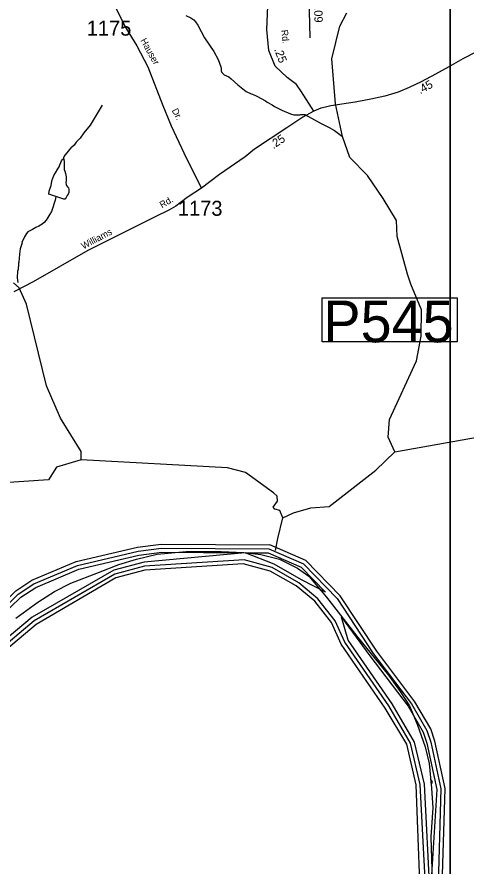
# Model space of a CAD drawing. Extents: x 1551653 to 1702041, y 811336 to 920032.
# Drawn here: x 1564838 to 1569264, y 841832 to 850193 of the extents above; entities that cross this region are included whole.
import ezdxf

# ---------------------------------------------------------------- set-up
doc = ezdxf.new("R2010")
doc.units = 0
for name, color, linetype in [('Old_Level_11', 7, 'Continuous'), ('Old_Level_17', 7, 'Continuous'), ('Old_Level_31', 7, 'Continuous'), ('Old_Level_32', 7, 'Continuous'), ('Old_Level_50', 7, 'Continuous'), ('Old_Level_52', 7, 'Continuous'), ('Old_Level_59', 7, 'Continuous'), ('Old_Level_60', 7, 'Continuous'), ('Old_Level_61', 7, 'Continuous'), ('Old_Level_62', 7, 'Continuous'), ('Old_Level_63', 7, 'Continuous'), ('Old_Level_8', 7, 'Continuous')]:
    doc.layers.add(name, color=color, linetype=linetype)

msp = doc.modelspace()

# ---------------------------------------------------------------- linework, layer by layer
at = {"layer": 'Old_Level_31'}
for p, q in [((1567981.814, 849323.404), (1567981.814, 849323.404)), ((1564859.91, 847517.633), (1564859.91, 847517.633))]:
    msp.add_line(p, q, dxfattribs=at)
msp.add_lwpolyline([(1567839.253, 847428.797), (1569167.183, 847428.797), (1569167.183, 846995.197), (1567839.253, 846995.197), (1567839.253, 847428.797)], dxfattribs=at)
at = {"layer": 'Old_Level_32'}
msp.add_line((1567706.962, 850436.136), (1567717.001, 849989.026), dxfattribs=at)
for points in [[(1565698.08, 850504.18), (1565911.883, 850079.073), (1566016.485, 849907.988), (1566123.637, 849701.155), (1566271.611, 849320.682), (1566353.167, 849120.476), (1566506.243, 848798.734), (1566651.484, 848508.82)], [(1567756.465, 849267.101), (1567636.692, 849456.514), (1567586.499, 849526.846), (1567496.151, 849597.178), (1567375.688, 849707.699), (1567315.457, 849863.434), (1567295.379, 850069.405), (1567310.437, 850456.231)], [(1569862.061, 850145.2), (1569803.462, 850098.002), (1569761.06, 850068.599), (1569700.362, 850027.401), (1569651.861, 850002.201), (1569569.263, 849957.202), (1569468.361, 849904.702), (1569355.563, 849850.302), (1569222.561, 849780.201), (1569085.261, 849702.1), (1568952.361, 849630.102), (1568813.064, 849554.102), (1568694.163, 849499.702), (1568585.462, 849451.3), (1568454.862, 849413.102), (1568316.365, 849385.103), (1568163.964, 849355.303), (1567923.164, 849316.803), (1567870.966, 849305.602), (1567826.963, 849296.1), (1567756.465, 849267.101)], [(1567756.465, 849267.101), (1567713.965, 849243.801), (1567649.464, 849206.701), (1567490.064, 849103.004), (1567172.765, 848891.502), (1567080.109, 848815.621), (1566828.63, 848641.12), (1566733.43, 848568.42), (1566651.484, 848508.82)], [(1566651.484, 848508.82), (1566511.569, 848414.905), (1566442.668, 848361.804), (1566400.168, 848330.505), (1566331.769, 848291.404), (1566204.568, 848227.205), (1565535.202, 847892.12), (1564996.772, 847586.504), (1564807.169, 847487.006)]]:
    msp.add_lwpolyline(points, dxfattribs=at)
at = {"layer": 'Old_Level_50'}
for p, q in [((1567971.847, 849330.495), (1567971.847, 849330.495)), ((1564861.143, 847515.569), (1564861.143, 847515.569))]:
    msp.add_line(p, q, dxfattribs=at)
at = {"layer": 'Old_Level_52'}
msp.add_lwpolyline([(1564827.484, 844271.619), (1565043.795, 844430.624), (1565207.132, 844536.628), (1565366.054, 844616.13), (1565639.753, 844722.133), (1565840.614, 844801.634), (1566012.78, 844854.635), (1566215.847, 844903.22), (1566502.79, 844929.721), (1566847.122, 844929.721), (1567067.847, 844920.887), (1567235.599, 844898.803), (1567421.008, 844854.635), (1567597.588, 844766.299), (1567707.951, 844686.797), (1567880.117, 844479.207), (1568180.303, 844094.945), (1568491.526, 843710.683), (1568606.303, 843551.679), (1568699.007, 843410.341), (1568774.054, 843229.252), (1568853.516, 843003.995), (1568891.038, 842840.574), (1568913.111, 842597.649), (1568926.354, 842403.31), (1568908.697, 842120.635), (1568919.733, 841687.789)], dxfattribs=at)
at = {"layer": 'Old_Level_59'}
for points in [[(1568553.499, 845909.87), (1568489.42, 846055.611), (1568500.493, 846229.392), (1568767.471, 846808.254), (1568812.48, 847050.267), (1568815.453, 847309.555), (1568711.492, 847561.154), (1568679.401, 847660.297), (1568576.465, 848030.057), (1568570.416, 848187.742), (1568439.49, 848407.096), (1568284.471, 848633.371), (1568112.432, 848810.896), (1568038.921, 849015.332), (1567970.564, 849338.343), (1567934.447, 849779.612), (1568014.417, 850103.031), (1568082.216, 850235.063)], [(1568553.499, 845909.87), (1569640.48, 846104.516), (1569908.483, 846207.349), (1570018.493, 846306.953), (1570173.41, 846628.782), (1570346.987, 847090.457), (1570290.495, 847210.72), (1570183.052, 847551.32), (1570206.424, 847731.142), (1570267.427, 847962.954), (1570316.759, 848274.353), (1570540.454, 848341.531), (1570804.105, 848417.305), (1571181.619, 848467.685), (1571347.726, 848487.837), (1571588.871, 848696.706), (1572056.714, 849146.29), (1572581.175, 849437.803), (1572779.999, 849528.487), (1573518.63, 849772.128), (1573732.499, 850003.581), (1573884.443, 850151.526), (1574087.93, 850283.395)], [(1565468.388, 845831.181), (1565469.413, 845913.202), (1565265.386, 846242.361), (1565128.411, 846560.244), (1564931.459, 847365.278), (1564859.383, 847524.296), (1564801.456, 847574.739)], [(1565468.388, 845831.181), (1565226.984, 845758.293), (1565148.964, 845634.862), (1564610.378, 845599.596), (1564343.602, 845846.458), (1564210.393, 845925.608), (1563689.815, 846009.536), (1563609.278, 845999.46), (1563314.418, 846219.498), (1563139.406, 846223.036), (1562226.412, 845952.675), (1561718.395, 845959.646), (1561353.403, 846081.96)], [(1567452.472, 845259.188), (1567555.943, 845309.214), (1567727.891, 845358.887), (1567908.257, 845371.073), (1568367.414, 845729.783), (1568553.499, 845909.87)], [(1567452.472, 845259.188), (1567422.207, 845332.14), (1567372.533, 845347.424), (1567357.249, 845366.529), (1567399.28, 845423.845), (1567395.46, 845473.519), (1567360.309, 845506.517), (1567083.48, 845706.51), (1566909.391, 845752.8), (1565468.388, 845831.181)], [(1567380.175, 844938.571), (1567403.102, 845057.024), (1567452.472, 845259.188)]]:
    msp.add_lwpolyline(points, dxfattribs=at)
at = {"layer": 'Old_Level_60'}
for points in [[(1563811.464, 842536.045), (1563824.383, 842844.341), (1563895.433, 843135.054), (1564238.383, 843840.433), (1564612.398, 844335.172), (1564824.422, 844540.994), (1564984.465, 844646.031), (1565420.406, 844830.937), (1566022.438, 844972.987), (1566256.403, 845001.079), (1567323.494, 844995.902)], [(1570744.48, 837724.242), (1570670.457, 837801.239), (1570442.439, 838180.073), (1570427.47, 838246.1), (1570191.455, 838684.142), (1569950.416, 839286.482), (1569838.458, 839597.393), (1569470.492, 840077.522), (1569188.443, 840775.93), (1569156.455, 840917.672), (1569132.463, 840934.588), (1569015.481, 841534.468), (1569047.469, 842594.126), (1568946.481, 843062.311), (1568906.496, 843181.344), (1568751.477, 843450.321), (1568375.411, 843947.111), (1568016.467, 844492.755), (1567679.464, 844840.933), (1567323.494, 844995.902)], [(1570893.451, 837048.288), (1570877.457, 837130.667), (1570255.431, 837908.122), (1569427.431, 839421.868), (1569048.495, 840319.176), (1569048.495, 840368.389), (1569008.407, 840444.719), (1568888.451, 840804.945), (1568843.443, 841137.436), (1568818.426, 841154.302), (1568764.497, 842632.676), (1568670.481, 843031.758), (1568459.483, 843387.319), (1568026.413, 844016.521), (1567929.423, 844228.597), (1567765.484, 844438.723), (1567584.423, 844590.103), (1567328.415, 844736.459), (1567062.463, 844807.51), (1566094.412, 844745.071), (1565809.389, 844668.741), (1565027.423, 844211.833), (1564605.426, 843859.246)]]:
    msp.add_lwpolyline(points, dxfattribs=at)
at = {"layer": 'Old_Level_61'}
for points in [[(1564642.438, 844308.618), (1564849.541, 844509.621), (1565003.432, 844610.609), (1565432.914, 844792.797), (1566029.41, 844933.566), (1566258.658, 844961.043), (1567315.087, 844955.916), (1567656.191, 844807.407), (1567985.095, 844467.636), (1568341.988, 843925.12), (1568718.053, 843428.176), (1568869.894, 843164.837), (1568907.829, 843051.7), (1569007.382, 842590.436), (1568975.496, 841535.698)], [(1567083.275, 844917.059), (1566089.285, 844824.888), (1565788.679, 844745.994), (1564987.028, 844280.885), (1564554.163, 843920.659), (1564383.355, 843720.58), (1564167.025, 843298.891), (1564021.643, 842805.381), (1563962.28, 842322.893), (1563891.742, 842541.992), (1563903.943, 842833.063), (1563971.097, 843107.782), (1564306.87, 843798.448), (1564672.478, 844282.064), (1564874.659, 844478.298), (1565022.297, 844575.186), (1565445.422, 844754.658), (1566036.485, 844894.093), (1566261.017, 844921.058), (1567083.275, 844917.059)], [(1567083.275, 844917.059), (1567306.68, 844915.982), (1567633.02, 844773.933), (1567870.47, 844528.536), (1567635.686, 844651.465), (1567368.093, 844805.921), (1567083.275, 844917.059)], [(1568883.325, 841141.178), (1568804.483, 842634.778), (1568709.441, 843040.935), (1568493.931, 843407.721), (1568061.374, 844036.309), (1567965.82, 844245.257), (1567797.062, 844463.33), (1567610.054, 844620.81), (1567348.305, 844771.164), (1567072.818, 844846.162), (1566091.849, 844785.005), (1565799.034, 844707.393), (1565007.226, 844246.385), (1564579.795, 843889.953)], [(1568902.6, 841535.135), (1568844.365, 842636.88), (1568748.298, 843050.111), (1568528.277, 843428.124), (1568096.233, 844056.148), (1568028.36, 844281.243), (1568308.564, 843903.127), (1568684.63, 843406.03), (1568833.19, 843148.331), (1568869.177, 843041.088), (1568967.191, 842586.795), (1568902.6, 841535.135)]]:
    msp.add_lwpolyline(points, dxfattribs=at)
at = {"layer": 'Old_Level_62'}
for points in [[(1566496.724, 850207.608), (1566548.5, 850185), (1566576.284, 850164.649), (1566594.021, 850146.451), (1566617.602, 850114.155), (1566682.091, 849987.382), (1566772.519, 849852.303), (1566815.58, 849775.819), (1566842.749, 849703.487), (1566846.543, 849687.442), (1566846.235, 849663.45), (1566852.079, 849645.406), (1566873.815, 849623.158), (1566919.541, 849602.602), (1566945.275, 849584.249), (1567008.534, 849523.502), (1567091.785, 849460.501), (1567139.46, 849435.894), (1567155.454, 849431.691), (1567195.234, 849413.184), (1567282.586, 849366.125), (1567298.478, 849353.924), (1567346.152, 849329.318), (1567369.938, 849313.068), (1567441.501, 849276.159), (1567529.059, 849239.095), (1567560.944, 849230.688), (1567596.931, 849228.227), (1567620.922, 849229.919), (1567629.022, 849233.815), (1567669.007, 849233.303), (1567827.922, 849145.386), (1567907.482, 849106.376), (1567961.001, 849073.721), (1568038.921, 849015.332)], [(1565674.465, 849326.345), (1565556.15, 849127.906), (1565495.967, 849051.422), (1565458.135, 848999.799), (1565419.893, 848959.917), (1565399.285, 848931.209), (1565375.089, 848907.578)], [(1565298.707, 848795.26), (1565299.63, 848810.28), (1565301.68, 848818.072), (1565315.009, 848836.117), (1565375.089, 848907.578)], [(1565219.352, 848423.962), (1565149.737, 848448.056), (1565154.145, 848478.66), (1565163.168, 848506.547), (1565172.088, 848532.486), (1565178.342, 848556.528), (1565184.186, 848589.747), (1565189.619, 848605.946), (1565201.205, 848631.833), (1565216.071, 848659.67), (1565239.55, 848697.092), (1565251.033, 848717.135), (1565259.85, 848736.564), (1565268.052, 848761.221), (1565274.203, 848776.754), (1565282.918, 848787.725), (1565291.53, 848795.414), (1565298.707, 848795.26)], [(1565298.707, 848795.26), (1565300.04, 848759.991), (1565300.553, 848715.597), (1565302.808, 848690.735), (1565307.012, 848674.331), (1565313.881, 848652.646), (1565318.802, 848634.294), (1565321.776, 848620.556), (1565322.083, 848599.64), (1565319.725, 848578.161), (1565318.905, 848563.141), (1565319.828, 848544.174), (1565324.236, 848534.946), (1565335.104, 848521.72), (1565343.409, 848509.161), (1565347.099, 848497.371), (1565348.125, 848482.966), (1565346.587, 848465.998), (1565341.768, 848449.799), (1565331.003, 848434.983), (1565320.238, 848416.888), (1565312.856, 848403.303), (1565308.242, 848399.459), (1565299.732, 848398.946), (1565219.352, 848423.962)], [(1565219.352, 848423.962), (1565212.073, 848388.796), (1565203.768, 848360.242), (1565188.594, 848317.438), (1565175.573, 848279.144), (1565162.04, 848250.642), (1565141.842, 848218.346), (1565123.183, 848192.612), (1565103.805, 848168.775), (1565085.966, 848154.114), (1565052.952, 848133.814), (1565021.989, 848118.691), (1564989.694, 848101.671), (1564944.89, 848077.629), (1564930.434, 848060.456), (1564911.261, 848028.519)], [(1564911.261, 848028.519), (1564886.552, 847972.848), (1564888.193, 847968.798), (1564869.841, 847909.076), (1564861.229, 847857.198), (1564856.307, 847777.279), (1564852.206, 847769.334), (1564851.796, 847737.345), (1564847.695, 847729.399), (1564847.388, 847705.46), (1564843.286, 847689.517), (1564840.518, 847625.54), (1564845.747, 847579.763)], [(1568909.195, 842640.749), (1568918.594, 842646.466), (1568922.798, 842656.411), (1568918.902, 842670.457), (1568909.059, 842684.605), (1568905.043, 842686.452)]]:
    msp.add_lwpolyline(points, dxfattribs=at)
at = {"layer": 'Old_Level_63'}
for points in [[(1569096.749, 874749.337), (1631612.821, 874749.337), (1631612.821, 831307.151), (1569096.749, 831307.151), (1569096.749, 874749.337)], [(1569096.749, 837125.444), (1552150.735, 837125.444), (1552150.735, 866094.075), (1569096.749, 866094.075), (1569096.749, 837125.444)]]:
    msp.add_lwpolyline(points, dxfattribs=at)

# ---------------------------------------------------------------- texts
at = {"layer": 'Old_Level_11'}
for s, rotation, p in [('Rd.', 276.6043, (1567436.345, 850063.502)), ('Hauser', 299.0440083, (1566049.006, 849962.233)), ('Dr.', 297.5093639, (1566357.555, 849272.812)), ('Rd.', 29.7549444, (1566263.476, 848308.736)), ('Williams', 27.9446528, (1565491.478, 847903.774))]:
    msp.add_text(s, height=65.6167, rotation=rotation, dxfattribs=at).set_placement(p)
at = {"layer": 'Old_Level_17'}
for s, rotation, p in [('.09', 271.2862972, (1567759.988, 850289.241)), ('.25', 291.1442417, (1567364.847, 849873.804)), ('.45', 28.6167944, (1568802.897, 849431.732)), ('.25', 33.6862389, (1567357.836, 848890.531))]:
    msp.add_text(s, height=82.0208, rotation=rotation, dxfattribs=at).set_placement(p)
at = {"layer": 'Old_Level_31'}
msp.add_text('P545', height=410.1042, dxfattribs=at).set_placement((1567851.134, 846989.651))
at = {"layer": 'Old_Level_8'}
for s, p in [('1175', (1565523.177, 850009.496)), ('1173', (1566419.42, 848235.43))]:
    msp.add_text(s, height=147.6375, dxfattribs=at).set_placement(p)

doc.saveas('drawing.dxf')
